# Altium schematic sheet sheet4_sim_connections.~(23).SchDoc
size A3; Author: Mauri Shadi; CompanyName: BFH; DrawnBy: Mauri Shadi; SheetNumber: 1; SheetTotal: 2
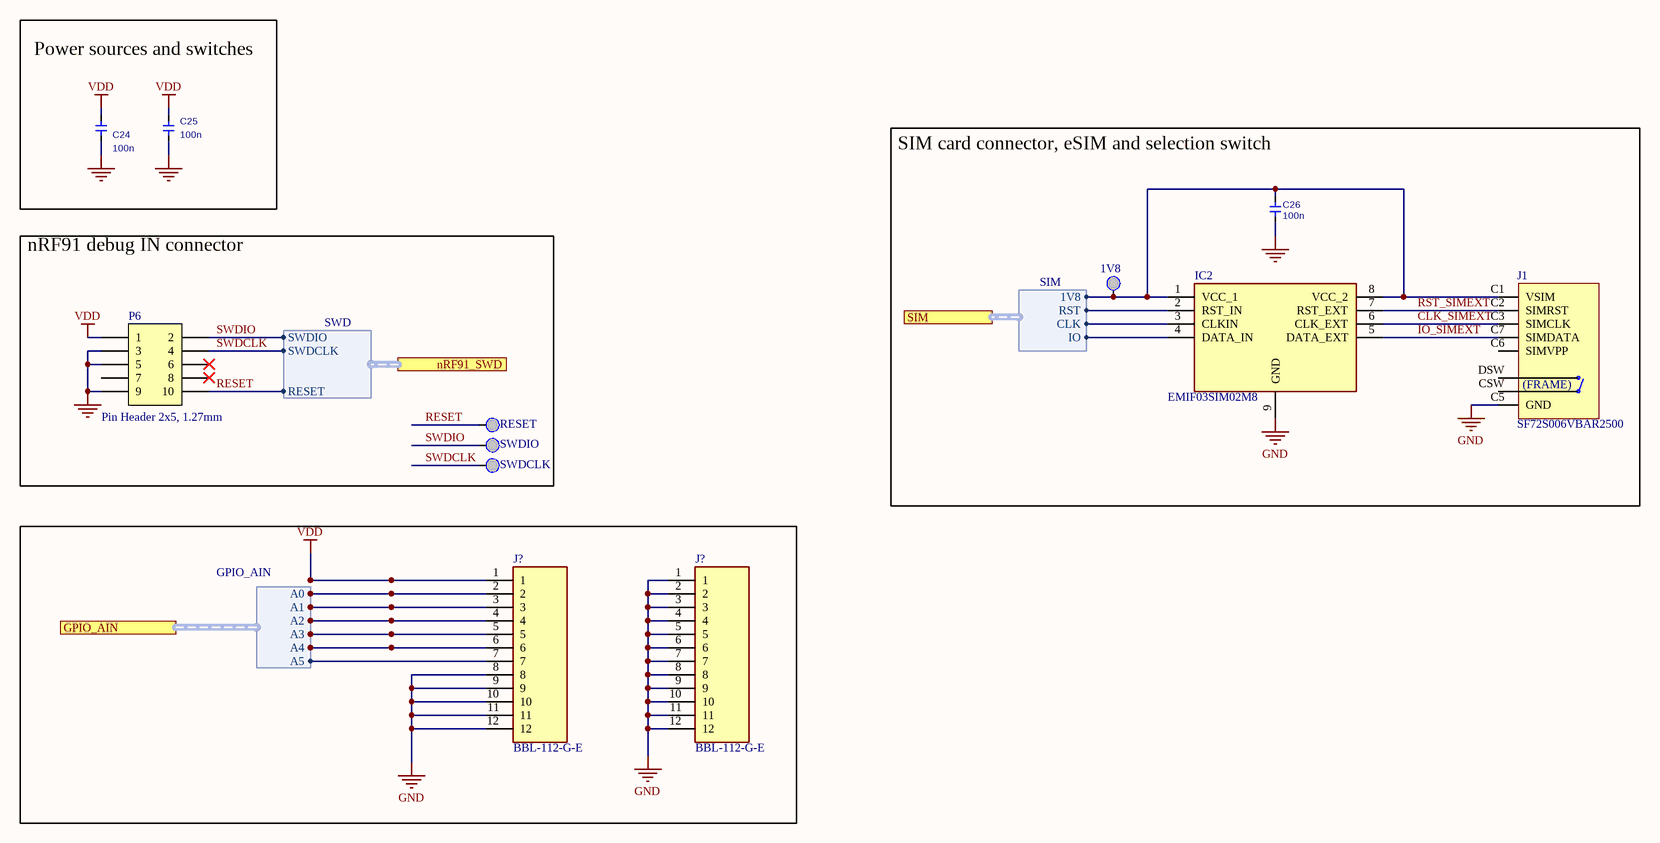
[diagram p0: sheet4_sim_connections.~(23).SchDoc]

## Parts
(Parts that share a designator on the sheet are numbered #1, #2 ... from top to bottom, then left to right.)
1V8  TESTPOINT_Black_Small  [Testpoint_Black_Small]  (value not drawn)
C24  100n  [0603(1608)C]
C25  100n  [0603(1608)C]
C26  100n  [0603(1608)C]
IC2  EMIF03SIM02M8  [SON40P150X170X60-9N-D]
J1  SF72S006VBAR2500  [SF72S006VBAR2500]
J?#1  BBL-112-G-E  [BBL-112-Y-X]
J?#2  BBL-112-G-E  [BBL-112-Y-X]
P6  Pin Header 2x5, 1.27mm  [HDR_2x5-SMD-1.27mm-K]
RESET  TESTPOINT_Black_Small  [Testpoint_Black_Small]  (value not drawn)
SWDCLK  TESTPOINT_Black_Small  [Testpoint_Black_Small]  (value not drawn)
SWDIO  TESTPOINT_Black_Small  [Testpoint_Black_Small]  (value not drawn)

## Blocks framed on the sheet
Power sources and switches: C24 C25
SIM card connector, eSIM and selection switch: 1V8 C26 IC2 J1
nRF91 debug IN connector: P6 RESET SWDCLK SWDIO

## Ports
GPIO_AIN (harness GPIO_AIN, see sheet2_nRF9160[7C]), nRF91_SWD (harness SWD, see sheet2_nRF9160[7D]), SIM (harness SIM, see sheet2_nRF9160[7C])

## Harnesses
SWD: SWDIO, SWDCLK, RESET
GPIO_AIN: A0, A1, A2, A3, A4, A5
SIM: CLK, IO, 1V8, RST

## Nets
GND: C24.2 C25.1 C26.1 IC2.9(GND) J1.0(GND) J1.C5(GND) J?#1.8 J?#1.9 J?#1.10 J?#1.11 J?#1.12 J?#2.1 J?#2.2 J?#2.3 J?#2.4 J?#2.5 J?#2.6 J?#2.7 J?#2.8 J?#2.9 J?#2.10 J?#2.11 J?#2.12 P6.3 P6.5 P6.9
VDD: C24.1 C25.2 J?#1.1 P6.1
CLK_SIMEXT: IC2.6(CLK_EXT) J1.C3(SIMCLK)
IO_SIMEXT: IC2.5(DATA_EXT) J1.C7(SIMDATA)
RESET: P6.10 RESET.1 ; port nRF91_SWD.RESET
RST_SIMEXT: IC2.7(RST_EXT) J1.C2(SIMRST)
SWDCLK: P6.4 SWDCLK.1 ; port nRF91_SWD.SWDCLK
SWDIO: P6.2 SWDIO.1 ; port nRF91_SWD.SWDIO
Net1V8_1: 1V8.1 C26.2 IC2.1(VCC_1) IC2.8(VCC_2) J1.C1(VSIM) ; port SIM.1V8
NetIC2_2: IC2.2(RST_IN) ; port SIM.RST
NetIC2_3: IC2.3(CLKIN) ; port SIM.CLK
NetIC2_4: IC2.4(DATA_IN) ; port SIM.IO
NetJ?#1_2: J?#1.2 ; port GPIO_AIN.A0
NetJ?#1_3: J?#1.3 ; port GPIO_AIN.A1
NetJ?#1_4: J?#1.4 ; port GPIO_AIN.A2
NetJ?#1_5: J?#1.5 ; port GPIO_AIN.A3
NetJ?#1_6: J?#1.6 ; port GPIO_AIN.A4
NetJ?#1_7: J?#1.7 ; port GPIO_AIN.A5

Not connected (* = marked no-connect by the designer): J1 C6(SIMVPP) CSW DSW; P6 6* 7 8*

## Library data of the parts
1V8 RESET SWDCLK SWDIO = TESTPOINT_Black_Small: PCB Test Point, Black, Through Hole Mount, 3.2 mm, Phosphor Bronze; Manufacturer: MULTICOMP; Manufacturer P/N: TEST-1(R)
C24 C25 = C0603_5_100n_25V: Cer Chip Capacitor / 100n/ +-5%/ 25V; Manufacturer Part Number: CC0603KRX7R8BB104; Manufacturer 1: Yageo; Special Value 1: +-5%; Capacitance: 100nF; Tolerance: 10%; Dielectric: X7R
C26 = C0603_5_100n_25V: Cer Chip Capacitor / 100n/ +-5%/ 25V; Manufacturer 1: Yageo; Manufacturer Part Number: CC0603KRX7R8BB104; Special Value 1: +-5%; Capacitance: 100nF; Tolerance: 10%; Dielectric: X7R
IC2 = EMIF03SIM02M8: Integrated Circuit; Manufacturer_Name: STMicroelectronics
J1 = SF72S006VBAR2500: n 8 (6 + 2) Position Card Connector NANO SIM Surface Mount, Right Angle Gold; Manufacturer: JAE Electronics; Part number IPS: 00000009956; Note: N.A.; Pad Count: 8
J?#1 J?#2 = BBL-112-G-E: Connector; Manufacturer_Name: SAMTEC
P6 = Pin Header 2x5 SMD, 1.27mm, KS: Pin Header 2x5, 1.27mm (50mil), SMD, Keying Shroud; Manufacturer: W-CON; Manufacturer Part Number: 3132-10MS0BK00R1; Part number IPS: 00000009968; Note: N.A.; Artikkelnr Noca: 55010009; Pad Count: 10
